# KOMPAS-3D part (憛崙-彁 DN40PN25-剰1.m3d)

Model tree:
1. Объединить компоненты:1  (labels: СЕНС-ПР DN40PN25-ДП1)

Referenced files in D:\Савин\!СЕНСОР\3D для заказчика\!Новый перечень\СЕНС-ПР\3. СЕНС-ПР-ДП\DN40\: СЕНС-ПР DN40PN25-ДП1.a3d
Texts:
  СЕНС-ПР DN40PN25-ДП1
  ООО НПП Сенсор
